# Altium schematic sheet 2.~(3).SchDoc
size 420 x 297 mm
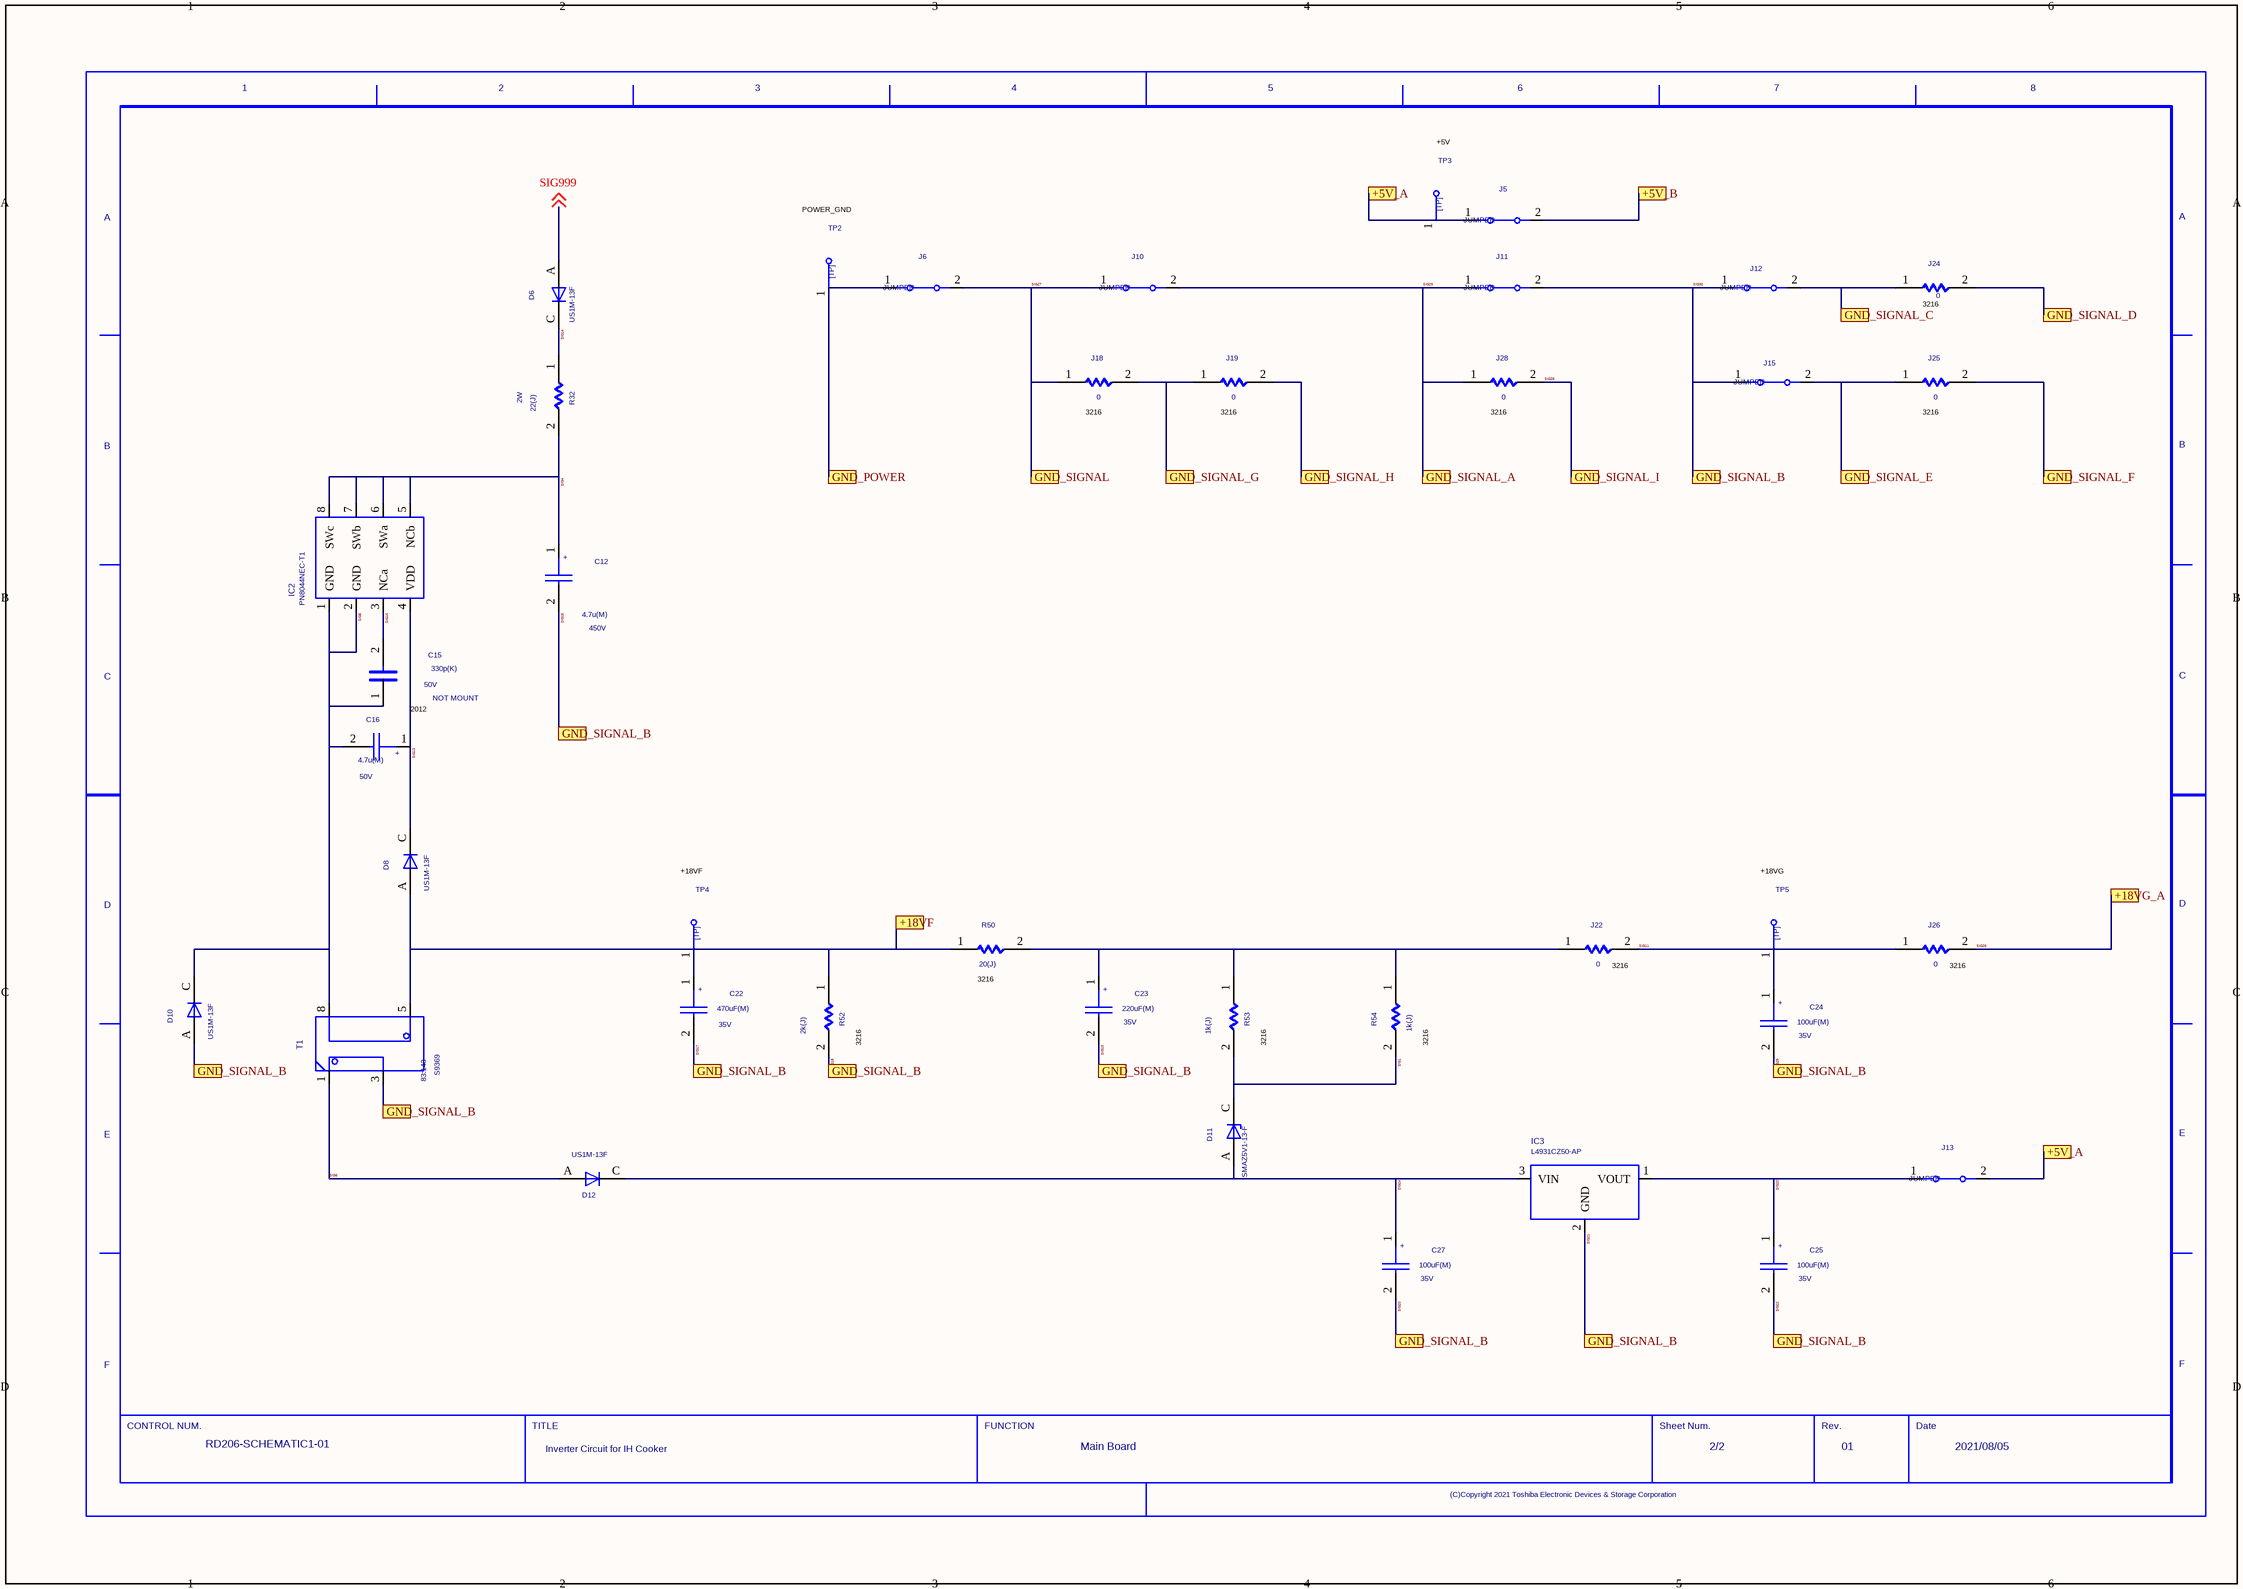
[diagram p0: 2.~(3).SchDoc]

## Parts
C12  VAL2: 450V  VAL1: 4.7u(M)  (hidden comment: CP)
C15  NOTMOUNT: NOT MOUNT  VAL2: 50V  VAL1: 330p(K)  (hidden comment: C)
C16  VAL2: 50V  VAL1: 4.7u(M)  (hidden comment: CP)
C22  VAL2: 35V  VAL1: 470uF(M)  (hidden comment: CP)
C23  VAL2: 35V  VAL1: 220uF(M)  (hidden comment: CP)
C24  VAL2: 35V  VAL1: 100uF(M)  (hidden comment: CP)
C25  VAL2: 35V  VAL1: 100uF(M)  (hidden comment: CP)
C27  VAL2: 35V  VAL1: 100uF(M)  (hidden comment: CP)
D6  VAL3: US1M-13F  (hidden comment: D)
D8  VAL3: US1M-13F  (hidden comment: D)
D10  VAL3: US1M-13F  (hidden comment: D)
D11  VAL3: SMAZ5V1-13-F  (hidden comment: ZD)
D12  VAL3: US1M-13F  (hidden comment: D)
IC2  VAL3: PN8044NEC-T1  (hidden comment: PN8044NEC_T1)
IC3  VAL3: L4931CZ50-AP  (hidden comment: 7805)
J5  VAL3: JUMPER  (hidden comment: JP)
J6  VAL3: JUMPER  (hidden comment: JP)
J10  VAL3: JUMPER  (hidden comment: JP)
J11  VAL3: JUMPER  (hidden comment: JP)
J12  VAL3: JUMPER  (hidden comment: JP)
J13  VAL3: JUMPER  (hidden comment: JP)
J15  VAL3: JUMPER  (hidden comment: JP)
J18  VAL1: 0  (hidden comment: R)
J19  VAL1: 0  (hidden comment: R)
J22  VAL1: 0  (hidden comment: R)
J24  VAL1: 0  (hidden comment: R)
J25  VAL1: 0  (hidden comment: R)
J26  VAL1: 0  (hidden comment: R)
J28  VAL1: 0  (hidden comment: R)
R32  VAL2: 2W  VAL1: 22(J)  (hidden comment: R)
R50  VAL1: 20(J)  (hidden comment: R)
R52  VAL1: 2k(J)  (hidden comment: R)
R53  VAL1: 1k(J)  (hidden comment: R)
R54  VAL1: 1k(J)  (hidden comment: R)
T1  VAL3: S9369  VAL1: 83:143  (hidden comment: EE10)
TP2  TP  (value not drawn)
TP3  TP  (value not drawn)
TP4  TP  (value not drawn)
TP5  TP  (value not drawn)
U?  DATE: 2021/08/05  FUNCTION: Main Board  TITLE: Inverter Circuit for IH Cooker  DRAWINGNUMBER: RD206-SCHEMATIC1-01  REVISION: 01  SHEETNUMBER: 2/2  (hidden comment: WAKU_DEF100)

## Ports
+5V_A, +5V_B, +18VF, +18VG_A, GND_POWER, GND_SIGNAL, GND_SIGNAL_A, GND_SIGNAL_B, GND_SIGNAL_C, GND_SIGNAL_D, GND_SIGNAL_E, GND_SIGNAL_F, GND_SIGNAL_G, GND_SIGNAL_H, GND_SIGNAL_I

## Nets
+5V_A: J5.1 J13.2 TP3.1 ; port +5V_A
+5V_B: J5.2 ; port +5V_B
+18VF: C22.1 D8.A R50.1 R52.1 T1.5 TP4.1 ; port +18VF
GND_POWER: J6.1 TP2.1 ; port GND_POWER
GND_SIGNAL_C: J12.2 J24.1 ; port GND_SIGNAL_C
GND_SIGNAL_D: J24.2 ; port GND_SIGNAL_D
GND_SIGNAL_E: J15.2 J25.1 ; port GND_SIGNAL_E
GND_SIGNAL_F: J25.2 ; port GND_SIGNAL_F
GND_SIGNAL_G: J18.2 J19.1 ; port GND_SIGNAL_G
GND_SIGNAL_H: J19.2 ; port GND_SIGNAL_H
SIG1: D11.C R53.2 R54.2
SIG4: C12.1 IC2.5(NCb) IC2.6(SWa) IC2.7(SWb) IC2.8(SWc) R32.2
SIG5: C15.1 C16.2 D10.C IC2.1(GND) IC2.2(GND) T1.8
SIG6: D12.A T1.1
SIG10: C23.1 J22.1 R50.2 R53.1 R54.1
SIG11: C24.1 J22.2 J26.1 TP5.1
SIG13: C16.1 D8.C IC2.4(VDD)
SIG14: D6.C R32.1
SIG15: C12.2 C22.2 C23.2 C24.2 C25.2 C27.2 D10.A IC3.2(GND) J11.2 J12.1 J15.1 R52.2 T1.3 ; port GND_SIGNAL_B  [also labelled SIG17, SIG18, SIG19, SIG20, SIG21, SIG22, SIG25, SIG30]
SIG16: C15.2 IC2.3(NCa)
SIG23: C25.1 IC3.1(VOUT) J13.1
SIG24: C27.1 D11.A D12.C IC3.3(VIN)
SIG26: J26.2 ; port +18VG_A
SIG27: J6.2 J10.1 J18.1 ; port GND_SIGNAL
SIG28: J28.2 ; port GND_SIGNAL_I
SIG29: J10.2 J11.1 J28.1 ; port GND_SIGNAL_A
SIG999: D6.A ; off-sheet SIG999

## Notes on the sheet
- +5V
- POWER_GND
- (near J24) 3216
- (near J18) 3216
- (near J19) 3216
- (near J28) 3216
- (near J25) 3216
- 2012
- +18VF
- +18VG
- (near R50) 3216
- (near J22) 3216
- (near J26) 3216
- (near R52) 3216
- (near R53) 3216
- (near R54) 3216

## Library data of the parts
C12 C22 = CP: PARTNAME: Part13601; SAVEAREA0: -1450,-153,20294,13055; SAVECOUNT: 52; TIME: 15:02:55; UPDATEUSER: fukuda-y; UPDATETIME: 16:13:42; OriginalSymbolOrigin: (2540,10160)
C15 = C: PARTNAME: Part6003; OriginalSymbolOrigin: (2540,7620)
C16 = CP: PARTNAME: Part13603; SAVEAREA0: -1450,-153,20294,13055; SAVECOUNT: 52; TIME: 15:02:55; UPDATEUSER: fukuda-y; UPDATETIME: 16:13:42; OriginalSymbolOrigin: (2540,10160)
C23 = CP: PARTNAME: Part13604; SAVEAREA0: -1450,-153,20294,13055; SAVECOUNT: 52; TIME: 15:02:55; UPDATEUSER: fukuda-y; UPDATETIME: 16:13:42; OriginalSymbolOrigin: (2540,10160)
C24 C25 C27 = CP: PARTNAME: Part13605; SAVEAREA0: -1450,-153,20294,13055; SAVECOUNT: 52; TIME: 15:02:55; UPDATEUSER: fukuda-y; UPDATETIME: 16:13:42; OriginalSymbolOrigin: (2540,10160)
D6 D8 D10 D12 = D: PARTNAME: Part13451; SAVEAREA0: -225,-91,12804,7836; SAVECOUNT: 3; TIME: 14:49:55; UPDATEUSER: 19870035; UPDATETIME: 14:20:16; OriginalSymbolOrigin: (5080,5080)
D11 = ZD: PARTNAME: Part13451; SAVEAREA0: -4630,-153,17114,13055; TIME: 14:49:55; UPDATEUSER: fukuda-y; UPDATETIME: 08:18:42; SAVECOUNT: 6; OriginalSymbolOrigin: (5080,5080)
IC2 = PN8044NEC_T1: PARTNAME: Part13001; TIME: 16:07:41; UPDATEUSER: t5459927; UPDATETIME: 09:18:27; SAVECOUNT: 2; SAVEAREA0: -16422,-15263,31006,6599; OriginalSymbolOrigin: (0,0); COMPONENTNAME: PN8044NEC-T1_PN8044NEC-T1.Normal_package
IC3 = 7805: PARTNAME: Part13002; TIME: 16:07:41; UPDATEUSER: t5459927; UPDATETIME: 09:17:01; SAVECOUNT: 2; SAVEAREA0: -5463,-13073,25154,1040; OriginalSymbolOrigin: (0,0)
J5 J10 J11 = JP: PARTNAME: Part13915; OriginalSymbolOrigin: (2540,5080)
J6 = JP: PARTNAME: Part13917; OriginalSymbolOrigin: (2540,5080)
J12 J13 = JP: PARTNAME: Part13913; OriginalSymbolOrigin: (2540,5080)
J15 = JP: PARTNAME: Part13911; OriginalSymbolOrigin: (2540,5080)
J18 J19 J22 J24-J26 J28 R50 R52-R54 = R: PARTNAME: Part4004; OriginalSymbolOrigin: (5080,5080)
R32 = R: PARTNAME: Part13401; OriginalSymbolOrigin: (5080,5080)
T1 = EE10: PARTNAME: Part13303; TIME: 16:07:41; UPDATEUSER: t5459927; UPDATETIME: 09:16:10; SAVECOUNT: 2; SAVEAREA0: -29920,-23417,50107,13472; OriginalSymbolOrigin: (0,0)
TP2-TP5 = TP: PARTNAME: Part13998; TIME: 16:12:21; UPDATEUSER: fukuda-y; UPDATETIME: 16:18:11; SAVECOUNT: 2; SAVEAREA0: -242,-92,12810,7836; OriginalSymbolOrigin: (0,7620)
U? = WAKU_DEF100: PLOTTIME: HH:MM; SAVEAREA0: 148187,-66180,486823,89919; TIME: 14:30:25; UPDATEUSER: t5459927; UPDATETIME: 11:15:29; SAVECOUNT: 6; OriginalSymbolOrigin: (10160,284480)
